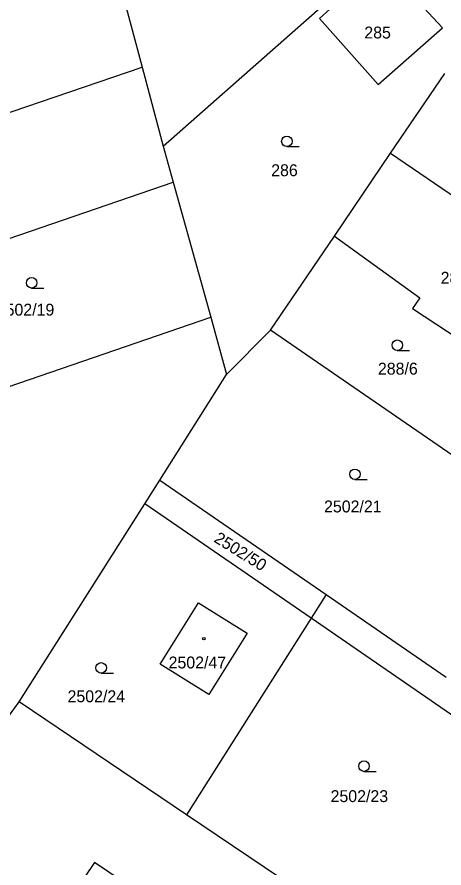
# Model space of a CAD drawing. Extents: x -558358 to -557517, y -1073785 to -1073189.
# Drawn here: x -558258 to -558197, y -1073448.9 to -1073327.3 of the extents above; entities that cross this region are included whole.
import ezdxf

# ---------------------------------------------------------------- set-up
doc = ezdxf.new("R2010")
doc.units = 0
for name, color, linetype in [('Hranice parcel', 7, 'Continuous'), ('Parcelní čísla', 7, 'Continuous'), ('Značky budov', 7, 'Continuous'), ('Značky kultur', 7, 'Continuous')]:
    doc.layers.add(name, color=color, linetype=linetype)

msp = doc.modelspace()

# ---------------------------------------------------------------- linework, layer by layer
at = {"layer": 'Hranice parcel'}
for p, q in [((-558245.27, -1073315.03), (-558240.15, -1073334.41)), ((-558305.76, -1073356.92), (-558240.15, -1073334.41)), ((-558240.15, -1073334.41), (-558237.16, -1073345.74)), ((-558204.65, -1073346.74), (-558196.91, -1073335.32)), ((-558237.16, -1073345.74), (-558235.73, -1073350.87)), ((-558212.67, -1073358.56), (-558204.65, -1073346.74)), ((-558204.65, -1073346.74), (-558176.94, -1073365.71)), ((-558300.65, -1073373.14), (-558235.73, -1073350.87)), ((-558235.73, -1073350.87), (-558230.35, -1073370.17)), ((-558221.79, -1073372.01), (-558212.67, -1073358.56)), ((-558212.67, -1073358.56), (-558200.47, -1073367.38)), ((-558294.64, -1073392.22), (-558230.35, -1073370.17)), ((-558230.35, -1073370.17), (-558228.07, -1073378.34)), ((-558228.07, -1073378.34), (-558221.79, -1073372.01)), ((-558193.18, -1073391.75), (-558221.79, -1073372.01)), ((-558237.63, -1073393.44), (-558228.07, -1073378.34)), ((-558239.77, -1073396.82), (-558237.63, -1073393.44)), ((-558237.63, -1073393.44), (-558213.88, -1073409.79)), ((-558257.7, -1073425.14), (-558239.77, -1073396.82)), ((-558216.02, -1073413.17), (-558239.77, -1073396.82)), ((-558213.88, -1073409.79), (-558216.02, -1073413.17)), ((-558213.88, -1073409.79), (-558196.71, -1073421.6)), ((-558216.02, -1073413.17), (-558233.8, -1073441.26)), ((-558274.97, -1073448.74), (-558257.7, -1073425.14)), ((-558233.8, -1073441.26), (-558257.7, -1073425.14)), ((-558202.26, -1073462.53), (-558233.8, -1073441.26))]:
    msp.add_line(p, q, dxfattribs=at)
for points in [[(-558237.16, -1073345.74), (-558202.67, -1073315.29), (-558195.58, -1073320.33), (-558174.53, -1073305.05)], [(-558197.27, -1073328.8), (-558205.94, -1073319.43), (-558214.79, -1073327.48), (-558206.42, -1073336.91), (-558197.27, -1073328.8)], [(-558200.47, -1073367.38), (-558201.52, -1073368.91), (-558186.39, -1073378.87)], [(-558232.07, -1073410.99), (-558225.13, -1073415.34), (-558230.62, -1073424.08), (-558237.55, -1073419.73), (-558232.07, -1073410.99)], [(-558202.26, -1073462.53), (-558188.73, -1073442.87), (-558187.31, -1073436.01), (-558191.04, -1073430.36), (-558216.02, -1073413.17)], [(-558252.58, -1073492.61), (-558249.44, -1073487.92), (-558239.75, -1073494.46), (-558236.97, -1073490.34), (-558223.28, -1073470.09), (-558220.49, -1073465.96), (-558246.94, -1073448.09), (-558263.73, -1073472.95)]]:
    msp.add_lwpolyline(points, dxfattribs=at)
at = {"layer": 'Značky budov'}
msp.add_circle((-558231.33, -1073416.12), 0.175, dxfattribs=at)
at = {"layer": 'Značky kultur'}
for p, q in [((-558219.47, -1073345.78), (-558217.72, -1073345.78)), ((-558255.92, -1073365.99), (-558254.17, -1073365.99)), ((-558203.7, -1073374.92), (-558201.95, -1073374.92)), ((-558209.75, -1073393.36), (-558208, -1073393.36)), ((-558245.99, -1073421.03), (-558244.24, -1073421.03)), ((-558208.46, -1073435.07), (-558206.71, -1073435.07))]:
    msp.add_line(p, q, dxfattribs=at)
for centre in [(-558219.47, -1073345.03), (-558255.92, -1073365.24), (-558203.7, -1073374.17), (-558209.75, -1073392.61), (-558245.99, -1073420.28), (-558208.46, -1073434.32)]:
    msp.add_circle(centre, 0.75, dxfattribs=at)

# ---------------------------------------------------------------- texts
at = {"layer": 'Parcelní čísla'}
for s, p in [('285', (-558208.41, -1073330.33)), ('286', (-558221.71, -1073350.01)), ('288/5', (-558197.51, -1073365.38)), ('2502/19', (-558260.9, -1073369.94)), ('288/6', (-558206.47, -1073378.37)), ('2502/21', (-558214.16, -1073398.06)), ('2502/47', (-558236.36, -1073420.36)), ('2502/24', (-558250.79, -1073425.19)), ('2502/23', (-558213.23, -1073439.46))]:
    msp.add_text(s, height=1.7, dxfattribs=at).set_placement(p)
msp.add_text('2502/50', height=1.7, rotation=328, dxfattribs=at).set_placement((-558230.02, -1073402.18))

doc.saveas('drawing.dxf')
